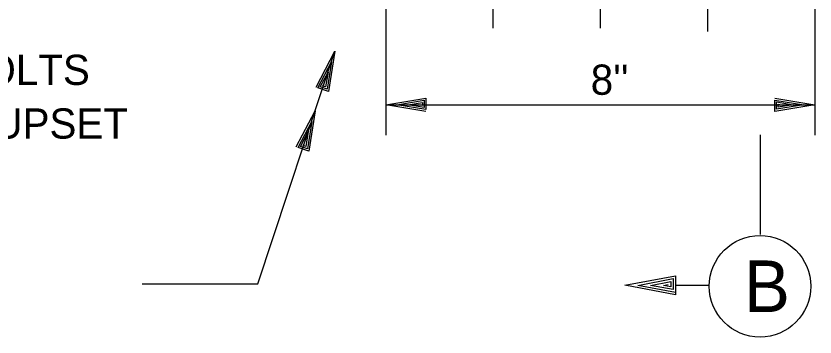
# Model space of a CAD drawing. Extents: x 22369.6 to 22389.4, y 22369.6 to 22386.
# Drawn here: x 22371.563 to 22372.804, y 22372.449 to 22372.947 of the extents above; entities that cross this region are included whole.
import ezdxf

# ---------------------------------------------------------------- set-up
doc = ezdxf.new("R2010")
doc.units = 0
for name, color, linetype in [('Level 1', 7, 'Continuous'), ('Level 2', 7, 'Continuous'), ('Level 3', 7, 'Continuous'), ('Level 4', 7, 'Continuous')]:
    doc.layers.add(name, color=color, linetype=linetype)

msp = doc.modelspace()

# ---------------------------------------------------------------- linework, layer by layer
at = {"layer": 'Level 1'}
for p, q in [((22372.4704, 22372.9282), (22372.4704, 22373.6772)), ((22372.3037, 22372.9282), (22372.3037, 22373.5746)), ((22372.6371, 22372.9231), (22372.6371, 22373.5692)), ((22372.1371, 22373.2803), (22372.1371, 22372.7626)), ((22372.8037, 22373.2), (22372.8037, 22372.7626)), ((22372.1371, 22372.8096), (22372.8037, 22372.8096))]:
    msp.add_line(p, q, dxfattribs=at)
at = {"layer": 'Level 2'}
for p, q in [((22372.058, 22372.8926), (22372.058, 22372.8926)), ((22372.0526, 22372.8762), (22372.0526, 22372.8762)), ((22372.1371, 22372.8096), (22372.1371, 22372.8096)), ((22372.1544, 22372.8096), (22372.1544, 22372.8096)), ((22372.7864, 22372.8096), (22372.7864, 22372.8096)), ((22372.8037, 22372.8096), (22372.8037, 22372.8096)), ((22372.0112, 22372.7515), (22372.0112, 22372.7515)), ((22371.9979, 22372.7443), (22371.9979, 22372.7443)), ((22372.0007, 22372.7434), (22372.0007, 22372.7434)), ((22372.0044, 22372.745), (22372.0044, 22372.745)), ((22372.0084, 22372.7464), (22372.0084, 22372.7464)), ((22372.0129, 22372.745), (22372.0129, 22372.745)), ((22372.0152, 22372.7414), (22372.0152, 22372.7414)), ((22372.0175, 22372.7378), (22372.0175, 22372.7378))]:
    msp.add_line(p, q, dxfattribs=at)
for points in [[(22371.7586, 22372.532), (22371.9383, 22372.532), (22372.058, 22372.8926)], [(22372.0286, 22372.8367), (22372.058, 22372.8926), (22372.0482, 22372.8302), (22372.0314, 22372.8357), (22372.0526, 22372.8762), (22372.0459, 22372.8338), (22372.0351, 22372.8373), (22372.0473, 22372.8603), (22372.0435, 22372.8374), (22372.0391, 22372.8388), (22372.0418, 22372.8439)], [(22372.1994, 22372.7993), (22372.1371, 22372.8096), (22372.1994, 22372.82), (22372.1994, 22372.8023), (22372.1544, 22372.8096), (22372.1967, 22372.8166), (22372.1967, 22372.8053), (22372.1711, 22372.8096), (22372.1941, 22372.8133), (22372.1941, 22372.8086), (22372.1884, 22372.8096)], [(22372.7414, 22372.82), (22372.8037, 22372.8096), (22372.7414, 22372.7993), (22372.7414, 22372.817), (22372.7864, 22372.8096), (22372.7441, 22372.8026), (22372.7441, 22372.814), (22372.7697, 22372.8096), (22372.7467, 22372.806), (22372.7467, 22372.8106), (22372.7524, 22372.8096)], [(22371.9979, 22372.7443), (22372.0273, 22372.8002), (22372.0175, 22372.7378), (22372.0007, 22372.7434), (22372.0219, 22372.7838), (22372.0152, 22372.7414), (22372.0044, 22372.745), (22372.0166, 22372.768), (22372.0129, 22372.745), (22372.0084, 22372.7464), (22372.0112, 22372.7515)]]:
    msp.add_lwpolyline(points, dxfattribs=at)
at = {"layer": 'Level 3'}
for p, q in [((22372.7183, 22372.7631), (22372.7183, 22372.6082)), ((22372.587, 22372.5296), (22372.6395, 22372.5296))]:
    msp.add_line(p, q, dxfattribs=at)
msp.add_lwpolyline([(22372.587, 22372.5186), (22372.587, 22372.5147), (22372.5083, 22372.5296), (22372.587, 22372.5443), (22372.587, 22372.5186), (22372.5284, 22372.5294), (22372.5832, 22372.5399), (22372.5832, 22372.5229), (22372.5482, 22372.5294), (22372.5796, 22372.5352), (22372.5796, 22372.5274), (22372.5683, 22372.5294), (22372.5757, 22372.5308)], dxfattribs=at)
msp.add_circle((22372.7183, 22372.5281), 0.0788, dxfattribs=at)

# ---------------------------------------------------------------- texts
msp.add_text('B', height=0.08, dxfattribs=at).set_placement((22372.6934, 22372.4881))
at = {"layer": 'Level 4'}
for s, height, p in [('AND TWO WASHERS, C.R.S.. AFTER BOLTS', 0.046875, (22370.3643, 22372.8404)), ("8''", 0.04688, (22372.4553, 22372.8251)), ('ARE TIGHTENED, SCAR THREADS OR UPSET', 0.046875, (22370.3643, 22372.7571))]:
    msp.add_text(s, height=height, dxfattribs=at).set_placement(p)

doc.saveas('drawing.dxf')
